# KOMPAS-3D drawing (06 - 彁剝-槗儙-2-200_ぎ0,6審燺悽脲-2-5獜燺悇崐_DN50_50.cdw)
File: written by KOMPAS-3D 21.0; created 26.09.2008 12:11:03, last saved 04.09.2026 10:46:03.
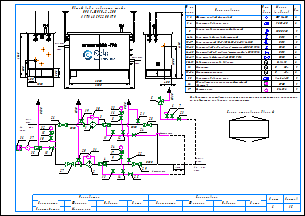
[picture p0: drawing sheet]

Sheets 1-2: A3, landscape

Document properties: Наименование: Макро:21; Автор: RaskoAdmin; Форматы листов документа: 2xA3; Полное имя файла: \\UR38nt01\Departments\КТО\КБ ПУРДГ\Заявки\Прайс-лист на типовые шкафы ГРПШ\ПРДГ_стандарт_20_03_2026\ПРДГ с РДНК\ПРДГ-ШУГО-2-200_до0,6МПа_Рвых-2-5кПа_РДНК_DN50_50.cdw

Title block, sheet 1: Наименование: Пункт учета газа / ПУГ-Ш-400-Р / ЛГТИ.485922.001ТУ; designation: ЛГТИ.03.4411141; sheet number: 1; Количество листов документа: 2; organisation: ООО "ЭЛЬСТЕР Газэлектроника"; Форматы листов документа: A3; stored path: C:\Рабочие документы\Компас\ПУГ\Схема.cdw; Разработал: Устинов; Проверил: Кошкин; Утвердил: Кошкин
Title block, sheet 2: sheet number: 2; stored path: D:\Рабочие документы\Заявки\ПУРДГ\ПУРДГ-ШУЭО-2-100-Р 4411220.cdw; designation, second copy: ЛГТИ.03.4411141-

Views: Вид 1, Вид 2
Referenced files: wcvoit.frw
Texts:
  Normal
  Вход
  газа
  PDI
  Выход
  Р=     кПа
  DN50
  DN20
  Импульс DN15
  ≥5DN
  HYSWLongFangSong
  № на
  схеме
  Усл.
  обозн.
  Марка
  (модель)
  Кол.
  Фильтр газовый фланцевый
  ФГ 16-50
  Регулятор давления газа
  РДНК-50
  Клапан предохранительный сбросной
  КПС DN20
  Кран шаровой газовый латунный
  DN15
  Кран кнопочный VE-РАСКО-НЗ-1,6-G1/2-М20
  Кран шаровой "под приварку" штуцерный DN20 PN16
  Кран шаровой "под приварку" штуцерный п/п DN15 PN16
  Кран шаровой фланцевый DN50 PN16
  Индикатор перепада давления
  Delta 15
  Манометр
  Манометр-напоромер
  0...     МПа
  0...     кПа
  Обогреватель газогорелочный шкафной
  (Эльтон")
  Счетчик газа
  Venio-A-15
  ОГШН
  BK-G1,6
  Общий вид и габариты шкафа
  ПРДГ-ШУГО-2-200
  Выход газа
  Вход газа
  Схема открывания дверей
  logo-rasko-ge.png
  Предприятие изготовитель может заменять комплектующие на аналогичные,
  не ухудшающие заявленных характеристик.
  Р=       МПа
  Должность
  Конструктор
  Фамилия
  Подпись
  Дата
  Согласовано
  Максимкин
  Лист
  Листов
  POLYLINE_STYLE_0.18_RGB_0_0_0
  POLYLINE_STYLE_0.50_RGB_0_0_0
  POLYLINE_STYLE_0.34_RGB_0_0_0
  PHANTOM_RGB_0_0_0_SC_1_THICK_0.18
  K5LT_THIN_RGB_0_0_0_THICK_0.18
  K5LT32769_RGB_0_0_0_THICK_0.18
  K5LT12_RGB_0_0_0_SC_1_THICK_0.18
  K5LT_DASHED_RGB_0_0_0_SC_1_THICK_0.18
  ACISOTGL_RGB_0_0_0_SC_0.8_THICK_0.25
  CONTINUOUS_RGB_0_127_31_THICK_0.3
  CONTINUOUS_RGB_0_0_255_THICK_0.35
  CONTINUOUS_RGB_255_0_0_THICK_0.35
  POLYLINE_STYLE_0.25_RGB_0_0_0
  CONTINUOUS_RGB_0_0_0_THICK_0.5
  POLYLINE_STYLE_0.35_RGB_0_0_255
  CONTINUOUS_RGB_0_0_0_THICK_0.4
  CONTINUOUS_RGB_0_0_0_THICK_0.35
  Без оформления
Dimensions and other numbers on the sheet: 1; 2; 3; 4; 5; 10; 27; 28; 29; 23; 8; 12; 18; 19; 20; 21; 22; 25; 24; 30; 31; 15; 16; 35; 36; 26; 6; 7; 11; 14; 13; 33; 1, 2; 3, 4; 6-14; 9; 15-17; 18-23; 24-25; 26-29; 30-31; 32; 33-34; 37; 1000; 400; 1050; 500; 305; 2000; 4130; 1565; 2300; 17; 34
